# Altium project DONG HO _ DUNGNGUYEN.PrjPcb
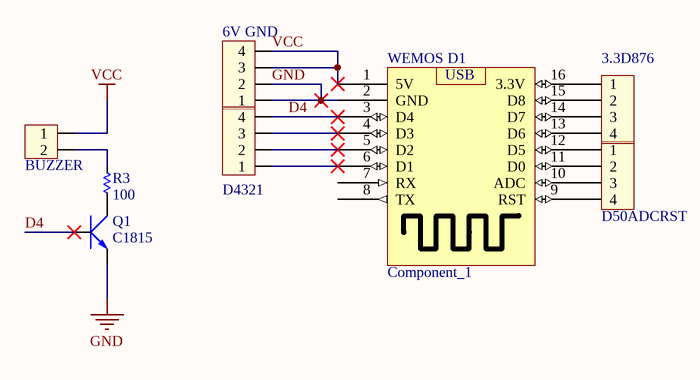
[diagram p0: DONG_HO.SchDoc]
1 sheet, 8 parts. Net scope: global (net labels, ports and power ports of the same name join across sheets).
Board file: PCB1 DONG HO DUNGNGUYEN.PcbDoc

## Sheet DONG_HO.SchDoc
size A

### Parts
3.3D876  Header 4  [HED4]  (value not drawn)
6V_GND  Header 4  [HED4]  (value not drawn)
BUZZER  Header 2  [HED2]  (value not drawn)
D50ADCRST  Header 4  [HED4]  (value not drawn)
D4321  Header 4  [HED4]  (value not drawn)
Q1  C1815  [QTO-92]
R3  100  [RES-1/8W-SMALL]
WEMOS_D1  Component_1  [ESP WEMOS MINI]

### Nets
GND: 6V_GND.1 6V_GND.2 Q1.1(E) WEMOS_D1.2(GND)
VCC: 6V_GND.3 6V_GND.4 BUZZER.1 WEMOS_D1.1(5V)
D4: D4321.4 Q1.3(B) WEMOS_D1.3(D4)
Net3.3D876_1: 3.3D876.1 WEMOS_D1.16(3.3V)
Net3.3D876_2: 3.3D876.2 WEMOS_D1.15(D8)
Net3.3D876_3: 3.3D876.3 WEMOS_D1.14(D7)
Net3.3D876_4: 3.3D876.4 WEMOS_D1.13(D6)
NetBUZZER_2: BUZZER.2 R3.2
NetD50ADCRST_1: D50ADCRST.1 WEMOS_D1.12(D5)
NetD50ADCRST_2: D50ADCRST.2 WEMOS_D1.11(D0)
NetD50ADCRST_3: D50ADCRST.3 WEMOS_D1.10(ADC)
NetD50ADCRST_4: D50ADCRST.4 WEMOS_D1.9(RST)
NetD4321_1: D4321.1 WEMOS_D1.6(D1)
NetD4321_2: D4321.2 WEMOS_D1.5(D2)
NetD4321_3: D4321.3 WEMOS_D1.4(D3)
NetQ1_2: Q1.2(C) R3.1

Not connected (* = marked no-connect by the designer): WEMOS_D1 7(RX) 8(TX)

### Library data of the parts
3.3D876 6V_GND D50ADCRST D4321 = Hed4: Header 4 (Green)
BUZZER = Hed2: Header 2 (Green)
Q1 = C1815: NPN 600mW, ECB
R3 = Res: Manufacturer: Generic Components; Class: Passive; SubClass: R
